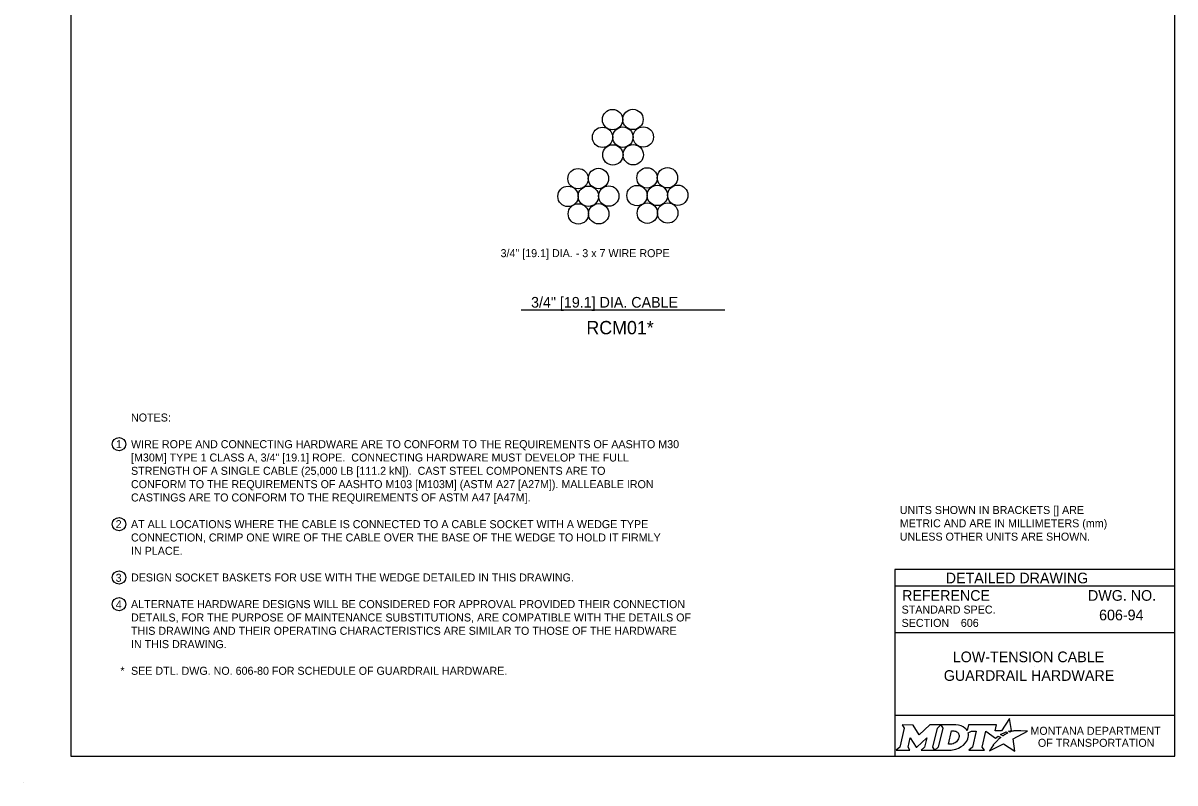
# Model space of a CAD drawing. Extents: x 49991.4 to 50021, y 49987.6 to 50011.4.
# Drawn here: x 49999.98 to 50008.61, y 49999.86 to 50005.56 of the extents above; entities that cross this region are included whole.
import ezdxf

# ---------------------------------------------------------------- set-up
doc = ezdxf.new("R2010")
doc.units = 0
doc.layers.add('Level 1', color=7, linetype='Continuous')
doc.layers.add('Level 2', color=7, linetype='Continuous')

msp = doc.modelspace()

# ---------------------------------------------------------------- linework, layer by layer
at = {"layer": 'Level 1'}
msp.add_line((49999.9766, 49999.8624), (49999.9766, 49999.8624), dxfattribs=at)
msp.add_lwpolyline([(50008.6146, 50011.2628), (50000.3356, 50011.2628), (50000.3356, 50000.0624), (50008.6146, 50000.0624)], close=True, dxfattribs=at)
for centre in [(50004.3975, 50004.8381), (50004.5503, 50004.8394), (50004.3221, 50004.7052), (50004.4749, 50004.7064), (50004.6277, 50004.7077), (50004.3996, 50004.5735), (50004.5524, 50004.5747), (50004.1385, 50004.3952), (50004.2913, 50004.3965), (50004.6559, 50004.4011), (50004.8087, 50004.4023), (50004.7334, 50004.2694), (50004.8862, 50004.2706), (50004.0632, 50004.2623), (50004.216, 50004.2635), (50004.3688, 50004.2648), (50004.5806, 50004.2681), (50004.1407, 50004.1306), (50004.2935, 50004.1318), (50004.6581, 50004.1364), (50004.8109, 50004.1377)]:
    msp.add_circle(centre, 0.0764, dxfattribs=at)
at = {"layer": 'Level 2'}
for p, q in [((50003.7117, 50003.4119), (50005.2385, 50003.4119)), ((50008.6146, 50001.4624), (50006.5146, 50001.4624)), ((50006.5146, 50001.4624), (50006.5146, 50000.0624)), ((50008.6146, 50001.3374), (50006.5146, 50001.3374)), ((50008.2507, 50001.1223), (50008.2507, 50001.1223)), ((50008.6146, 50000.9874), (50006.5146, 50000.9874)), ((50007.0089, 50001.0629), (50007.0089, 50001.0629)), ((50007.5646, 50000.7383), (50007.5646, 50000.7383)), ((50008.6146, 50000.3693), (50006.5146, 50000.3693))]:
    msp.add_line(p, q, dxfattribs=at)
for points in [[(50006.5701, 50000.2974), (50006.5842, 50000.274), (50006.5507, 50000.1307), (50006.525, 50000.1082), (50006.6266, 50000.1082), (50006.6131, 50000.131), (50006.6293, 50000.2011), (50006.673, 50000.1321), (50006.6783, 50000.1321), (50006.7534, 50000.2016), (50006.737, 50000.1305), (50006.7123, 50000.1085), (50006.8139, 50000.1085), (50006.8001, 50000.1318), (50006.8333, 50000.2742)], [(50006.8333, 50000.2742), (50006.8586, 50000.2974), (50006.7762, 50000.2974), (50006.6966, 50000.2244), (50006.6521, 50000.2971), (50006.5701, 50000.2974)], [(50006.9722, 50000.2974), (50006.8586, 50000.2974), (50006.8733, 50000.2745), (50006.8394, 50000.1307), (50006.8139, 50000.1085), (50006.9245, 50000.1085)], [(50007.3771, 50000.2447), (50007.3668, 50000.2503), (50007.3784, 50000.2531), (50007.39, 50000.2551), (50007.3726, 50000.3452), (50007.3131, 50000.2539), (50007.2658, 50000.2532), (50007.2761, 50000.2973), (50007.0669, 50000.2974), (50007.0568, 50000.2549), (50007.051, 50000.2632)], [(50006.9962, 50000.2107), (50006.995, 50000.2026), (50006.9918, 50000.1933), (50006.9876, 50000.1851), (50006.982, 50000.1776), (50006.9755, 50000.1707), (50006.9676, 50000.1644), (50006.9593, 50000.1597), (50006.9502, 50000.1558), (50006.9411, 50000.1535), (50006.9319, 50000.1526), (50006.916, 50000.1526), (50006.9396, 50000.2526), (50006.9556, 50000.2526), (50006.9632, 50000.252), (50006.9708, 50000.2501), (50006.9774, 50000.2471), (50006.9835, 50000.2429), (50006.9883, 50000.2379), (50006.992, 50000.2319), (50006.9947, 50000.2257), (50006.9963, 50000.2183), (50006.9963, 50000.2153), (50006.9962, 50000.2107)], [(50007.0636, 50000.2383), (50007.0882, 50000.2514), (50007.1251, 50000.2514), (50007.0965, 50000.1309), (50007.069, 50000.1082), (50007.1852, 50000.1082), (50007.1682, 50000.1311), (50007.1964, 50000.2513), (50007.2677, 50000.1996), (50007.2888, 50000.2147), (50007.3085, 50000.2038)], [(50007.2527, 50000.1479), (50007.2374, 50000.1235), (50007.2327, 50000.116), (50007.2269, 50000.1074), (50007.2246, 50000.1031), (50007.3299, 50000.1562), (50007.4138, 50000.1011), (50007.4007, 50000.1938), (50007.5076, 50000.2522), (50007.4583, 50000.253), (50007.4282, 50000.2534), (50007.4074, 50000.2537), (50007.4006, 50000.2522), (50007.3957, 50000.251), (50007.3873, 50000.2487), (50007.3771, 50000.2447)], [(50007.3267, 50000.2171), (50007.3243, 50000.2154), (50007.306, 50000.225), (50007.3163, 50000.2307), (50007.3204, 50000.2329), (50007.329, 50000.2369), (50007.3347, 50000.2395), (50007.3426, 50000.2425), (50007.3499, 50000.2452), (50007.3617, 50000.2378), (50007.3577, 50000.2357), (50007.3531, 50000.2332), (50007.3489, 50000.231), (50007.3439, 50000.2281), (50007.342, 50000.227), (50007.3393, 50000.2254), (50007.3368, 50000.224), (50007.3345, 50000.2224), (50007.3319, 50000.2206), (50007.3292, 50000.2188), (50007.3267, 50000.2171)], [(50006.9702, 50000.1158), (50006.9786, 50000.1184), (50006.9916, 50000.1238), (50007.012, 50000.1348)], [(50007.2666, 50000.164), (50007.2666, 50000.164)]]:
    msp.add_lwpolyline(points, dxfattribs=at)
for centre in [(50000.6962, 50002.4037), (50000.6962, 50001.8037), (50000.6962, 50001.4037), (50000.6962, 50001.2037)]:
    msp.add_circle(centre, 0.05, dxfattribs=at)
for centre, radius, start, end in [((50006.9953, 50000.219), 0.0709, 339.53292, 15.85821), ((50006.9513, 50000.2363), 0.1183, 300.91025, 339.13831)]:
    msp.add_arc(centre, radius, start, end, dxfattribs=at)
for centre, major_axis, ratio, start_param, end_param in [((50006.9701, 50000.25), (0.0834, -0.0037), 0.568097, 0.61298, 1.570796), ((50007.0257, 50000.2573), (0.0361, -0.0295), 0.469099, 1.225588, 1.570796), ((50007.2974, 50000.1941), (-0.0112, -0.0097), 0.021651, 3.157348, 6.283185), ((50006.9248, 50000.2568), (0, 0.1484), 0.987302, 3.139398, 3.456847), ((50007.2597, 50000.1559), (-0.00694, -0.00806), 0.008222, 0, 3.137361), ((50007.2764, 50000.1742), (-0.0098, -0.0102), 0.016458, 3.141593, 6.279097)]:
    msp.add_ellipse(centre, major_axis=major_axis, ratio=ratio, start_param=start_param, end_param=end_param, dxfattribs=at)

# ---------------------------------------------------------------- texts
for s, height, p in [('3/4" [19.1] DIA. - 3 x 7 WIRE ROPE', 0.06, (50003.5576, 50003.8064)), ('3/4" [19.1] DIA. CABLE', 0.08, (50003.7862, 50003.4279)), ('RCM01*', 0.1, (50004.2009, 50003.2279)), ('NOTES:', 0.06, (50000.7862, 50002.5737)), ('1', 0.06, (50000.6736, 50002.3738)), ('WIRE ROPE AND CONNECTING HARDWARE ARE TO CONFORM TO THE REQUIREMENTS OF AASHTO M30', 0.06, (50000.7862, 50002.3737)), ('[M30M] TYPE 1 CLASS A, 3/4" [19.1] ROPE.  CONNECTING HARDWARE MUST DEVELOP THE FULL', 0.06, (50000.7862, 50002.2737)), ('STRENGTH OF A SINGLE CABLE (25,000 LB [111.2 kN]).  CAST STEEL COMPONENTS ARE TO ', 0.06, (50000.7862, 50002.1737)), ('CONFORM TO THE REQUIREMENTS OF AASHTO M103 [M103M] (ASTM A27 [A27M]). MALLEABLE IRON', 0.06, (50000.7862, 50002.0737)), ('CASTINGS ARE TO CONFORM TO THE REQUIREMENTS OF ASTM A47 [A47M].', 0.06, (50000.7862, 50001.9737)), ('UNITS SHOWN IN BRACKETS [] ARE ', 0.06, (50006.5511, 50001.8801)), ('METRIC AND ARE IN MILLIMETERS (mm) ', 0.06, (50006.5511, 50001.7801)), ('2', 0.06, (50000.6711, 50001.7737)), ('AT ALL LOCATIONS WHERE THE CABLE IS CONNECTED TO A CABLE SOCKET WITH A WEDGE TYPE', 0.06, (50000.7862, 50001.7737)), ('CONNECTION, CRIMP ONE WIRE OF THE CABLE OVER THE BASE OF THE WEDGE TO HOLD IT FIRMLY', 0.06, (50000.7862, 50001.6737)), ('UNLESS OTHER UNITS ARE SHOWN.', 0.06, (50006.5511, 50001.6801)), ('IN PLACE.', 0.06, (50000.7862, 50001.5737)), ('3', 0.06, (50000.671, 50001.3714)), ('DESIGN SOCKET BASKETS FOR USE WITH THE WEDGE DETAILED IN THIS DRAWING.', 0.06, (50000.7862, 50001.3737)), ('DETAILED DRAWING', 0.0799, (50006.8956, 50001.3599)), ('REFERENCE', 0.08, (50006.5682, 50001.229)), ('DWG. NO.', 0.08, (50007.9624, 50001.229)), ('4', 0.06, (50000.6722, 50001.1714)), ('ALTERNATE HARDWARE DESIGNS WILL BE CONSIDERED FOR APPROVAL PROVIDED THEIR CONNECTION', 0.06, (50000.7862, 50001.1737)), ('STANDARD SPEC.', 0.06, (50006.5649, 50001.133)), ('606-94', 0.08, (50008.0456, 50001.0823)), ('DETAILS, FOR THE PURPOSE OF MAINTENANCE SUBSTITUTIONS, ARE COMPATIBLE WITH THE DETAILS OF', 0.06, (50000.7862, 50001.0737)), ('SECTION', 0.06, (50006.5649, 50001.033)), ('606', 0.06, (50007.0089, 50001.0329)), ('THIS DRAWING AND THEIR OPERATING CHARACTERISTICS ARE SIMILAR TO THOSE OF THE HARDWARE', 0.06, (50000.7862, 50000.9737)), ('IN THIS DRAWING.', 0.06, (50000.7862, 50000.8737)), ('LOW-TENSION CABLE', 0.08, (50006.9484, 50000.7683)), ('*', 0.06, (50000.7064, 50000.6737)), ('SEE DTL. DWG. NO. 606-80 FOR SCHEDULE OF GUARDRAIL HARDWARE.', 0.06, (50000.7862, 50000.6737)), ('GUARDRAIL HARDWARE', 0.08, (50006.8812, 50000.6283)), ('MONTANA DEPARTMENT', 0.06, (50007.5308, 50000.2236)), ('OF TRANSPORTATION', 0.06, (50007.587, 50000.1336))]:
    msp.add_text(s, height=height, dxfattribs=at).set_placement(p)

doc.saveas('drawing.dxf')
